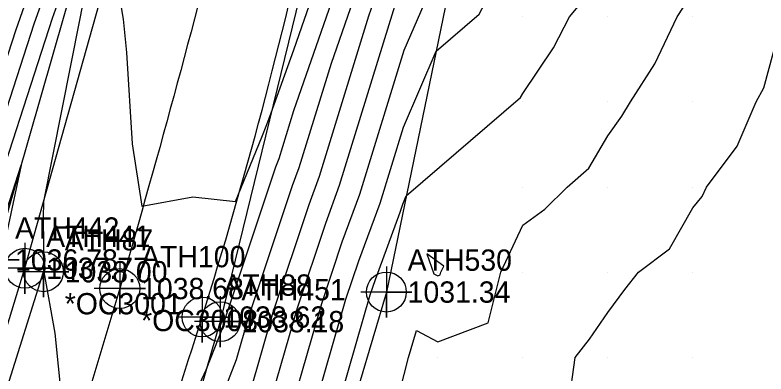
# Model space of a CAD drawing. Extents: x 1213164 to 1213550, y 766120 to 766870.
# Drawn here: x 1213390.3 to 1213478.6, y 766738.1 to 766780.2 of the extents above; entities that cross this region are included whole.
import ezdxf

# ---------------------------------------------------------------- set-up
doc = ezdxf.new("R2010")
doc.units = 0
for name, color, linetype in [('Default', 7, 'Continuous'), ('Exist DTM Breakline', 7, 'Continuous'), ('Exist DTM Breakline Cogo Elevation', 7, 'Continuous'), ('Exist DTM Breakline Cogo Number', 7, 'Continuous'), ('Exist DTM Breakline Cogo Point CELL', 7, 'Continuous'), ('Exist DTM Crownline', 7, 'Continuous'), ('Exist DTM Crownline Cogo Comment', 7, 'Continuous'), ('Exist DTM Crownline Cogo Elevation', 7, 'Continuous'), ('Exist DTM Crownline Cogo Number', 7, 'Continuous'), ('Exist DTM Crownline Cogo Point CELL', 7, 'Continuous'), ('Exist DTM QL2 LIDAR Elevation Point', 7, 'Continuous'), ('Exist Roads EOP', 7, 'Continuous'), ('Exist Roads EOP Cogo Comment', 7, 'Continuous'), ('Exist Roads EOP Cogo Elevation', 7, 'Continuous'), ('Exist Roads EOP Cogo Number', 7, 'Continuous'), ('Exist Roads EOP Cogo Point CELL', 7, 'Continuous')]:
    doc.layers.add(name, color=color, linetype=linetype)

msp = doc.modelspace()

# ---------------------------------------------------------------- linework, layer by layer
at = {"layer": 'Default'}
for points in [[(1213407.121, 766726.367), (1213412.78, 766738.536), (1213414.717, 766743.514), (1213414.943, 766744.295), (1213420.982, 766762.391), (1213421.345, 766763.374), (1213423.08, 766769), (1213429.851, 766788.437), (1213428.115, 766790.46), (1213428.46, 766791.982), (1213429.189, 766794.641), (1213432.107, 766794.195), (1213435.794, 766807.048), (1213441.705, 766821.733), (1213441.807, 766822.483), (1213445.026, 766823.602)], [(1213406.915, 766715.546), (1213416.344, 766739.776), (1213417.797, 766744.803), (1213422.929, 766760.184), (1213423.719, 766762.321), (1213427.493, 766774.555), (1213431.978, 766787.427), (1213428.893, 766791.02), (1213428.912, 766791.058), (1213428.916, 766791.101), (1213429.527, 766793.815), (1213429.566, 766793.852), (1213434.398, 766793.113), (1213436.828, 766801.582), (1213444.584, 766820.849), (1213444.638, 766821.25), (1213448.796, 766822.695)], [(1213417.971, 766736.038), (1213420.651, 766745.31), (1213424.877, 766757.976), (1213426.094, 766761.269), (1213431.906, 766780.109), (1213434.104, 766786.417), (1213432.592, 766788.178), (1213433.028, 766789.06), (1213433.113, 766790.061), (1213433.44, 766791.514), (1213434.358, 766792.388), (1213436.689, 766792.031), (1213437.861, 766796.117), (1213447.462, 766819.966), (1213447.469, 766820.017), (1213452.565, 766821.788)], [(1213419.598, 766732.3), (1213423.505, 766745.817), (1213426.825, 766755.768), (1213428.468, 766760.216), (1213436.144, 766785.095), (1213436.305, 766785.469), (1213436.491, 766785.74), (1213437.143, 766787.062), (1213437.31, 766789.021), (1213437.353, 766789.213), (1213438.554, 766790.355), (1213439.045, 766790.985), (1213445.628, 766807.084), (1213448.839, 766810.887), (1213452.142, 766816.379), (1213453.546, 766819.913), (1213456.335, 766820.882)], [(1213421.225, 766728.562), (1213426.358, 766746.325), (1213428.773, 766753.561), (1213430.843, 766759.163), (1213436.058, 766776.068), (1213440.351, 766786.037), (1213440.617, 766786.424), (1213440.676, 766787.084), (1213442.087, 766790.175), (1213442.282, 766790.426), (1213442.981, 766792.135), (1213449.958, 766800.396), (1213457.134, 766812.327), (1213460, 766819.541), (1213460.14, 766819.86), (1213460.187, 766820)], [(1213422.851, 766724.824), (1213429.212, 766746.832), (1213430.721, 766751.353), (1213433.217, 766758.11), (1213435.973, 766767.041), (1213439.81, 766775.952), (1213444.889, 766780.311), (1213446.229, 766782.929), (1213450, 766787.756), (1213451.006, 766788.994), (1213451.51, 766790), (1213455.256, 766794.744), (1213457.857, 766800), (1213460, 766803.813), (1213462.314, 766807.686), (1213463.093, 766810), (1213465.195, 766814.805), (1213466.976, 766820)], [(1213424.478, 766721.086), (1213432.066, 766747.34), (1213432.669, 766749.145), (1213435.592, 766757.057), (1213435.887, 766758.014), (1213436.299, 766758.97), (1213449.746, 766770.512), (1213450, 766771.007), (1213453.629, 766776.371), (1213455.504, 766780), (1213457.52, 766782.48), (1213460, 766787.434), (1213461.032, 766788.968), (1213461.443, 766790), (1213464.863, 766795.137), (1213466.403, 766800), (1213467.748, 766802.252), (1213470, 766808.933), (1213470.32, 766809.68), (1213470.389, 766810), (1213473.119, 766816.881), (1213473.967, 766820), (1213474.094, 766820.154)], [(1213432.563, 766724.347), (1213436.581, 766740.012), (1213437.508, 766743.17), (1213440, 766741.826), (1213445.936, 766744.064), (1213447.428, 766750), (1213450, 766755.519), (1213452.593, 766757.407), (1213455.201, 766760), (1213457.761, 766762.239), (1213460, 766766.007), (1213461.662, 766768.338), (1213462.651, 766770), (1213465.513, 766774.487), (1213468.136, 766780), (1213468.886, 766781.114), (1213470, 766783.912), (1213471.886, 766788.114), (1213472.323, 766790), (1213474.452, 766795.548), (1213475.417, 766800), (1213476.793, 766803.207), (1213478.245, 766810), (1213478.744, 766811.256)], [(1213379.596, 766735.396), (1213382.063, 766742.965), (1213385.261, 766751.214), (1213386.624, 766755.027), (1213394.707, 766779.838), (1213395.493, 766782.064), (1213401.198, 766799.68), (1213401.231, 766799.805), (1213402.663, 766805.491), (1213402.605, 766803.059), (1213402.275, 766799.279), (1213399.269, 766786.732), (1213397.9, 766779.789), (1213393.663, 766758.303), (1213393.59, 766756.355), (1213393.67, 766750.16), (1213393.673, 766750.105), (1213393.681, 766750.051), (1213394.967, 766742.851), (1213396.502, 766727.724)], [(1213402.481, 766783.012), (1213403.013, 766779.716), (1213403.404, 766775.797), (1213404.078, 766765.088), (1213405.203, 766757.767), (1213411.21, 766758.866), (1213416.219, 766758.296), (1213419.326, 766765.848), (1213419.907, 766767.359), (1213420.415, 766768.74), (1213423.086, 766776.13), (1213427.725, 766789.446)], [(1213384.687, 766760.909), (1213390.425, 766778.523), (1213393.617, 766787.563)], [(1213385.656, 766757.968), (1213392.566, 766779.181), (1213394.555, 766784.814)], [(1213455.413, 766734.587), (1213456.17, 766740), (1213457.863, 766742.137), (1213460, 766745.293), (1213462.008, 766747.992), (1213463.592, 766750), (1213467.263, 766752.737), (1213470, 766757.566), (1213471.09, 766758.91), (1213471.611, 766760), (1213475.195, 766764.805), (1213477.462, 766770), (1213478.357, 766771.643), (1213480, 766777.714)], [(1213373.535, 766714.544), (1213382.55, 766738.51), (1213383.607, 766741.753), (1213387.349, 766751.403), (1213387.593, 766752.085), (1213391.009, 766762.571), (1213388.609, 766751.23), (1213388.063, 766745.588), (1213387.112, 766739.862), (1213386.651, 766736.068)], [(1213440.306, 766749.694), (1213440.383, 766750), (1213440.718, 766750.718), (1213438.715, 766752.16), (1213439.544, 766749.824), (1213440, 766749.578), (1213440.306, 766749.694)]]:
    msp.add_lwpolyline(points, dxfattribs=at)
at = {"layer": 'Exist DTM Breakline'}
for points in [[(1213346.628, 766614.521), (1213356.147, 766642.326), (1213365.891, 766675.979), (1213376.506, 766712.04), (1213387.804, 766751.444), (1213401.652, 766799.525), (1213406.478, 766827.991)], [(1213348.967, 766613.21), (1213359.36, 766641.078), (1213368.166, 766674.744), (1213379.292, 766710.798), (1213391.46, 766750.473), (1213404.901, 766798.24), (1213409.089, 766827.096)], [(1213432.48, 766824.565), (1213426.442, 766793.398), (1213414.418, 766744.202), (1213402.864, 766704.233), (1213391.111, 766668.435), (1213399.916, 766666.943)], [(1213447.885, 766819.836), (1213441.941, 766786.26), (1213433.964, 766747.677), (1213424.337, 766715.269), (1213411.9, 766681.742)]]:
    msp.add_lwpolyline(points, dxfattribs=at)
at = {"layer": 'Exist DTM Breakline Cogo Point CELL'}
for points in [[(1213387.804, 766754.444), (1213387.804, 766748.444), (1213387.804, 766751.444), (1213390.804, 766751.444), (1213384.804, 766751.444)], [(1213391.46, 766753.473), (1213391.46, 766747.473), (1213391.46, 766750.473), (1213394.46, 766750.473), (1213388.46, 766750.473)], [(1213433.964, 766750.677), (1213433.964, 766744.677), (1213433.964, 766747.677), (1213436.964, 766747.677), (1213430.964, 766747.677)], [(1213414.418, 766747.202), (1213414.418, 766741.202), (1213414.418, 766744.202), (1213417.418, 766744.202), (1213411.418, 766744.202)]]:
    msp.add_lwpolyline(points, dxfattribs=at)
for centre in [(1213391.46, 766750.473), (1213433.964, 766747.677), (1213414.418, 766744.202)]:
    msp.add_circle(centre, 2.344, dxfattribs=at)
at = {"layer": 'Exist DTM Crownline'}
msp.add_line((1213402.624, 766748.087), (1213390.559, 766707.958), dxfattribs=at)
msp.add_spline([(1213422.346, 766829.784), (1213415.509, 766796.457), (1213402.624, 766748.087)], degree=3, dxfattribs=at)
at = {"layer": 'Exist DTM Crownline Cogo Point CELL'}
msp.add_lwpolyline([(1213402.624, 766751.087), (1213402.624, 766745.087), (1213402.624, 766748.087), (1213405.624, 766748.087), (1213399.624, 766748.087)], dxfattribs=at)
msp.add_circle((1213402.624, 766748.087), 2.344, dxfattribs=at)
at = {"layer": 'Exist DTM QL2 LIDAR Elevation Point'}
for p, q in [((1213450, 766780), (1213450, 766780)), ((1213460, 766780), (1213460, 766780)), ((1213470, 766780), (1213470, 766780)), ((1213450, 766770), (1213450, 766770)), ((1213460, 766770), (1213460, 766770)), ((1213470, 766770), (1213470, 766770)), ((1213450, 766760), (1213450, 766760)), ((1213460, 766760), (1213460, 766760)), ((1213470, 766760), (1213470, 766760)), ((1213440, 766750), (1213440, 766750)), ((1213450, 766750), (1213450, 766750)), ((1213460, 766750), (1213460, 766750)), ((1213470, 766750), (1213470, 766750)), ((1213440, 766740), (1213440, 766740)), ((1213450, 766740), (1213450, 766740)), ((1213460, 766740), (1213460, 766740)), ((1213470, 766740), (1213470, 766740))]:
    msp.add_line(p, q, dxfattribs=at)
at = {"layer": 'Exist Roads EOP'}
msp.add_line((1213381.4, 766711.123), (1213393.642, 766750.06), dxfattribs=at)
msp.add_spline([(1213390.233, 766668.75), (1213399.517, 766704.888), (1213412.301, 766744.745), (1213425.35, 766793.621), (1213431.775, 766824.817)], degree=3, dxfattribs=at)
at = {"layer": 'Exist Roads EOP Cogo Point CELL'}
for points in [[(1213393.642, 766753.06), (1213393.642, 766747.06), (1213393.642, 766750.06), (1213396.642, 766750.06), (1213390.642, 766750.06)], [(1213412.301, 766747.745), (1213412.301, 766741.745), (1213412.301, 766744.745), (1213415.301, 766744.745), (1213409.301, 766744.745)]]:
    msp.add_lwpolyline(points, dxfattribs=at)
for centre in [(1213393.642, 766750.06), (1213412.301, 766744.745)]:
    msp.add_circle(centre, 2.344, dxfattribs=at)

# ---------------------------------------------------------------- texts
at = {"layer": 'Exist DTM Breakline Cogo Elevation'}
for s, p in [('1036.78', (1213390.304, 766750.194)), ('1037.77', (1213393.96, 766749.223)), ('1031.34', (1213436.464, 766746.427)), ('1038.18', (1213416.918, 766742.952))]:
    msp.add_text(s, height=2.5, dxfattribs=at).set_placement(p)
at = {"layer": 'Exist DTM Breakline Cogo Number'}
for s, p in [('ATH442', (1213390.304, 766753.944)), ('ATH441', (1213393.96, 766752.973)), ('ATH530', (1213436.464, 766750.177)), ('ATH451', (1213416.918, 766746.702))]:
    msp.add_text(s, height=2.5, dxfattribs=at).set_placement(p)
at = {"layer": 'Exist DTM Crownline Cogo Comment'}
msp.add_text('*OC3008', height=2.5, dxfattribs=at).set_placement((1213405.124, 766743.087))
at = {"layer": 'Exist DTM Crownline Cogo Elevation'}
msp.add_text('1038.68', height=2.5, dxfattribs=at).set_placement((1213405.124, 766746.837))
at = {"layer": 'Exist DTM Crownline Cogo Number'}
msp.add_text('ATH100', height=2.5, dxfattribs=at).set_placement((1213405.124, 766750.587))
at = {"layer": 'Exist Roads EOP Cogo Comment'}
msp.add_text('*OC3001', height=2.5, dxfattribs=at).set_placement((1213396.142, 766745.06))
at = {"layer": 'Exist Roads EOP Cogo Elevation'}
for s, p in [('1038.00', (1213396.142, 766748.81)), ('1038.62', (1213414.801, 766743.495))]:
    msp.add_text(s, height=2.5, dxfattribs=at).set_placement(p)
at = {"layer": 'Exist Roads EOP Cogo Number'}
for s, p in [('ATH87', (1213396.142, 766752.56)), ('ATH88', (1213414.801, 766747.245))]:
    msp.add_text(s, height=2.5, dxfattribs=at).set_placement(p)

doc.saveas('drawing.dxf')
